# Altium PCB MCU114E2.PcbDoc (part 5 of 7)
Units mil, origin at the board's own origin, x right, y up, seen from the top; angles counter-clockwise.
Board outline 4153.94 x 2313.28 mil, 8 copper layers (Top Layer, GND 2, Signal Layer 3, Power 4, Power 5, Signal Layer 6, GND 7, Bottom), stack 61.2 mil thick; 444 components, 418 nets, 1811 pads, 981 vias.
Unrouted connection lines stored in the file: 3.
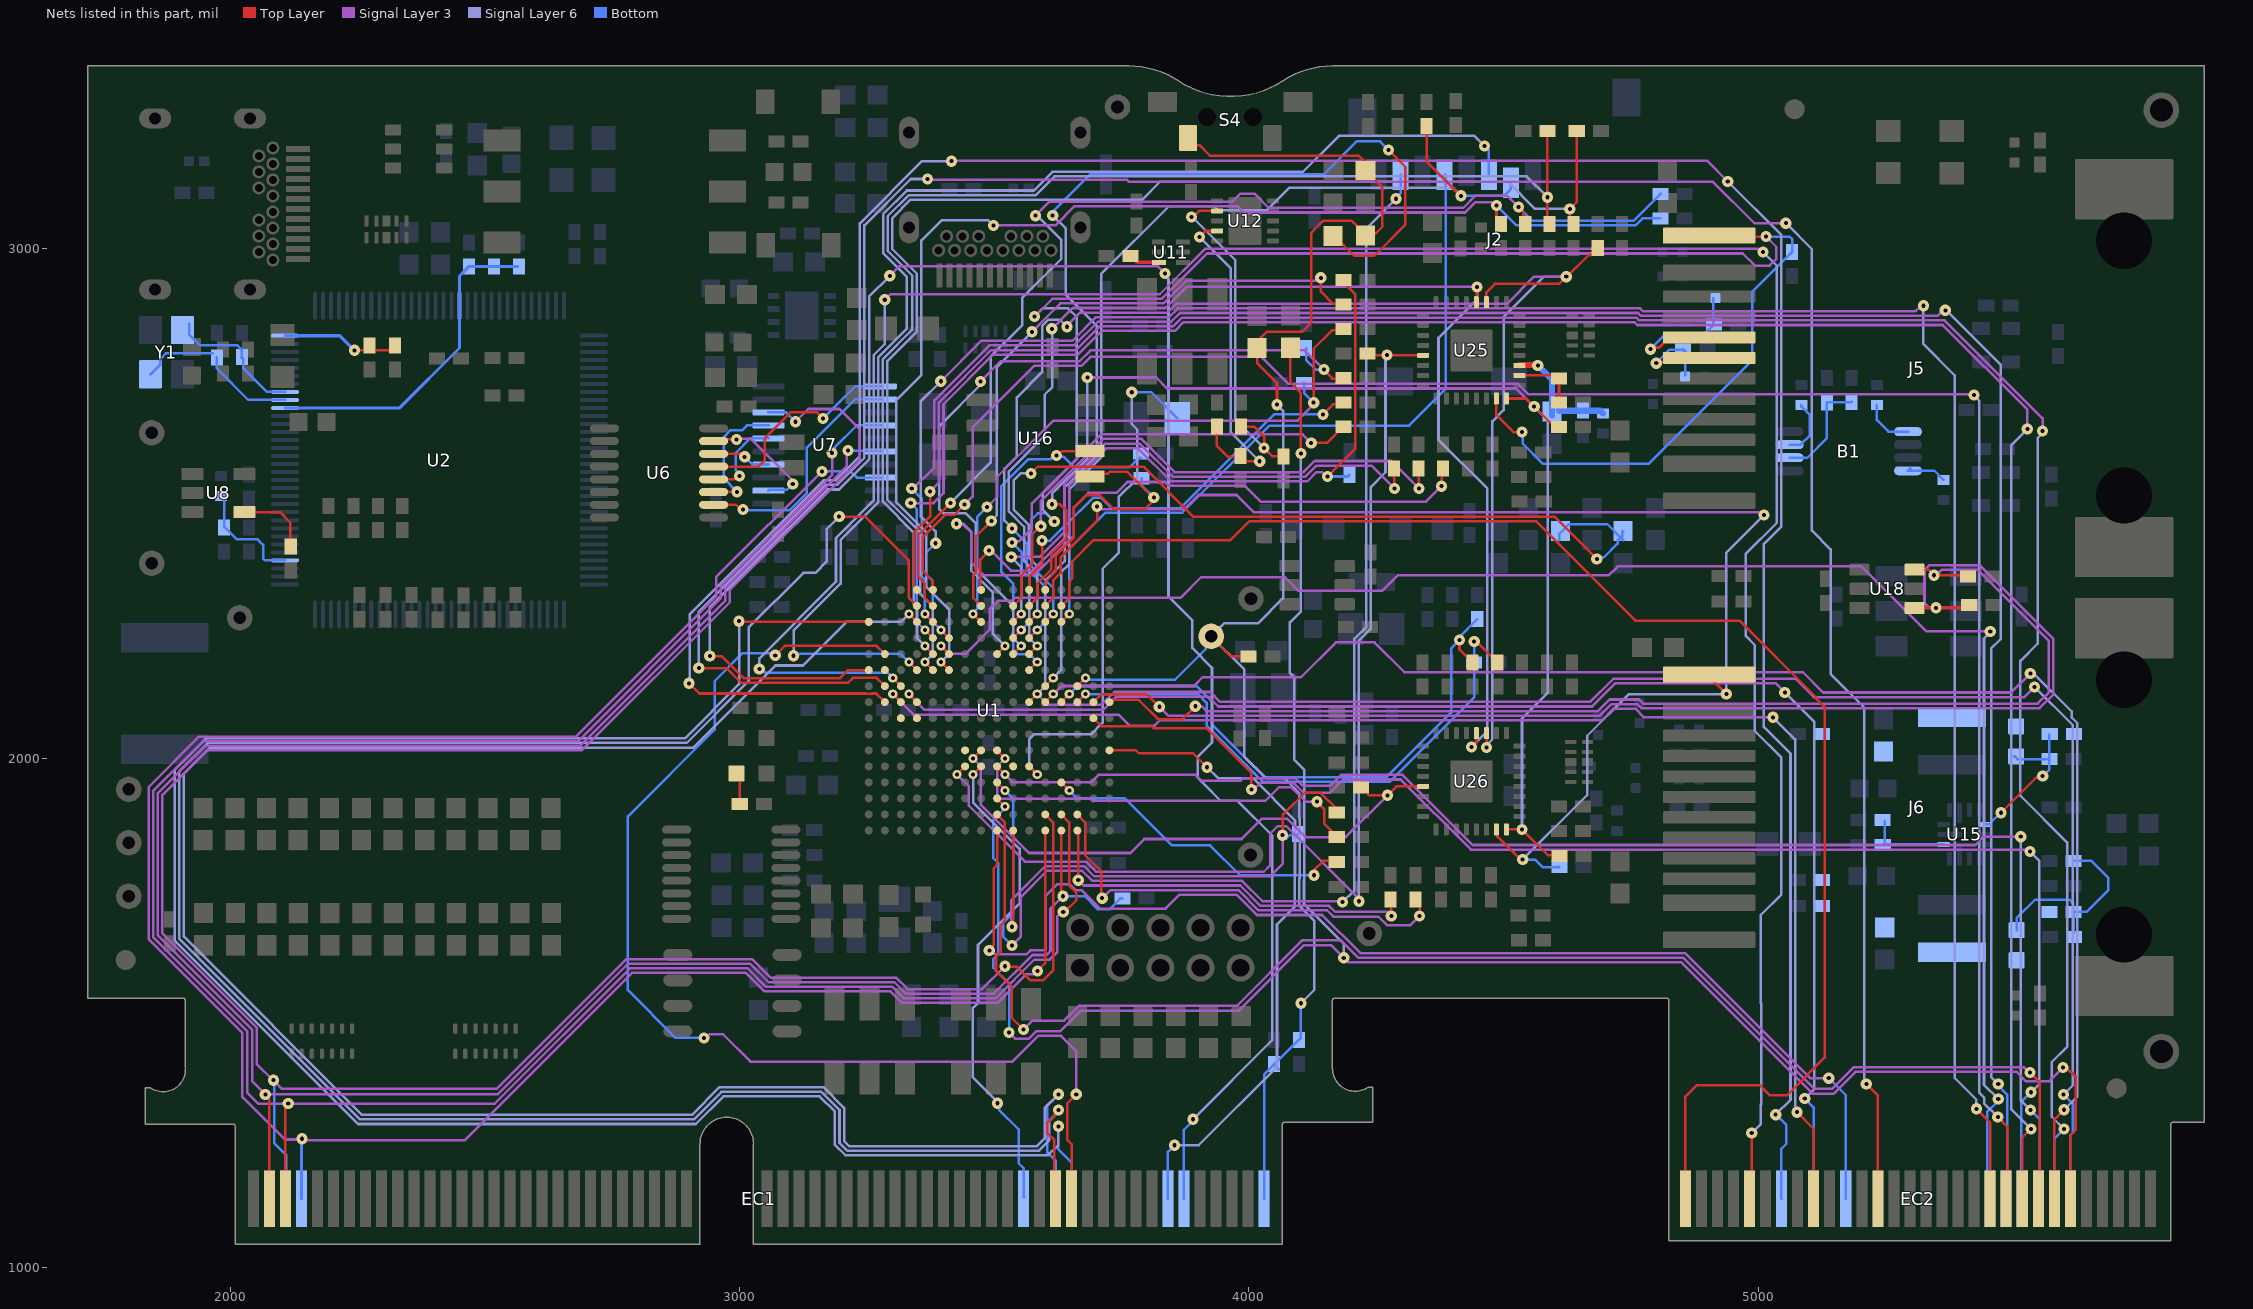
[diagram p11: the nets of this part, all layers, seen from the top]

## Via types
v1: diameter 22, hole 8, Top Layer to Bottom, tented both sides, 810 vias
v2: diameter 18, hole 8, Top Layer to Bottom, tented both sides, 153 vias
v3: diameter 19.68, hole 7.87, Top Layer to Bottom, tented both sides, 10 vias
v4: diameter 19.68, hole 7.87, Top Layer to Bottom, tented bottom, 4 vias
v5: diameter 19.68, hole 7.87, Top Layer to Bottom, tented top, 4 vias

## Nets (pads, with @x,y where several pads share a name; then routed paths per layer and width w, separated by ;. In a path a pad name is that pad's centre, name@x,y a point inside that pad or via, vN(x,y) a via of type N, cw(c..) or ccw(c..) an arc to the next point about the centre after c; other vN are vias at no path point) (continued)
MCU_GPIO90: EC2.159 U1.D6 | length 4360.5
  Top Layer w5: v2(3395.33,2251.77) U1.D6@3411.08,2236.02 ; v1(5428,1311.82) 5454.91,1284.92 EC2.159@5454.91,1135.27
  Signal Layer 3 w5: v1(3395,2740) 3474.27,2819.27 3653,2819.27 3699.51,2865.78 3843.42,2865.78 3860.64,2883 4767.76,2883 4773.31,2877.45 5308.42,2877.45 5319.23,2888.27 v1(5323.83,2888.27)
  Signal Layer 6 w5: v1(3385,2422) 3385,2445.4 3356,2474.4 3356,2701 v1(3395,2740) ; v1(5323.83,2888.27) 5323.83,2813.27 5385.37,2751.73 5385.37,1372.27 5428,1329.64 v1(5428,1311.82)
  Bottom w5: v1(3385,2422) 3366.4,2403.4 3366.4,2360.6 3379.33,2347.67 3379.33,2267.76 v2(3395.33,2251.77)
MCU_GPIO91: EC2.160 U1.E6 | length 3392.4
  Top Layer w5: v2(3395.33,2220.27) U1.E6@3411.08,2204.52
  Signal Layer 3 w5: v2(3395.33,2220.27) 3410.83,2204.77 3443.42,2204.77 3490.82,2252.17 3490.82,2292.84 3506.88,2308.9 3534.22,2308.9 3540.09,2314.77 3865.58,2314.77 3906.13,2355.31 3930.88,2355.31 4070.83,2355.32 4097.6,2328.54 4261.38,2328.54 4292.1,2359.27 4706.56,2359.27 4724.06,2376.77 5202.08,2376.77 5329.85,2249 v1(5455,2249)
  Signal Layer 6 w5: v1(5455,2249) 5455,2247.18 5442.83,2235.01 5442.83,1358.94 v1(5470.83,1330.94)
  Bottom w5: EC2.160@5454.91,1135.27 5449.05,1141.12 5449.05,1305.49 v1@5467.83,1324.27
MCU_GPIO92: EC2.161 U1.A5 | length 4038.8
  Top Layer w5: U1.A5@3379.58,2330.51 3379.58,2347.42 3359.83,2367.17 3359.83,2434.54 3403.11,2477.82 3421.39,2477.82 v1(3441.83,2498.27) ; v1(5469.94,1295.74) 5488.33,1277.35 5488.33,1135.27 EC2.161@5486.4,1135.27
  Signal Layer 3 w5: v1(3441.83,2498.27) 3457.33,2513.77 3457.33,2649.33 3578.27,2770.27 3671,2770.27 3688.5,2787.77 3873.97,2787.77 4024.96,2787.77 4077.96,2734.77 4528.06,2734.77 4548.56,2714.27 5421.73,2714.27 v1(5423,2713)
  Signal Layer 6 w5: v1(5423,2713) 5423,2712.13 5433.56,2701.57 5433.56,1343.28 5443.2,1333.64 5443.2,1322.48 v1(5469.94,1295.74)
MCU_GPIO93: EC2.162 U1.C5 | length 4347.2
  Top Layer w5: v2(3363.83,2283.26) U1.C5@3379.58,2267.52
  Signal Layer 3 w5: v1(3337.98,2529.48) 3340.67,2529.48 3382.33,2571.14 3382.33,2702.33 3490.27,2810.27 3552.37,2810.27 3656.72,2810.27 3703.24,2856.78 3847.15,2856.78 3864.37,2874 4764.03,2874 4769.58,2868.45 5351.42,2868.45 5362.23,2879.27 v1(5366.83,2879.27)
  Signal Layer 6 w5: v1(5366.83,2879.27) 5368.83,2879.27 5475.37,2772.73 5475.37,2233.54 5456.94,2215.1 5456.94,1374.16 v1(5470.83,1360.27)
  Bottom w5: v1(3337.98,2529.48) 3357.4,2510.07 3357.4,2356.88 3363.83,2350.44 v2(3363.83,2283.26) ; v1@5467.83,1360.27 5488.33,1339.77 5488.33,1137.2 EC2.162@5486.4,1135.27
MCU_GPIO94: EC2.163 U1.D5 | length 4374.6
  Top Layer w5: v2(3363.83,2251.77) U1.D5@3379.58,2236.02 ; EC2.163@5517.9,1135.27 5517.9,1255.33 v1(5534.83,1272.27)
  Signal Layer 3 w5: v1(3336.05,2500.98) 3380.98,2500.98 3400.33,2520.33 3400.33,2694.88 3497.73,2792.27 3544.92,2792.27 3664.18,2792.27 3710.69,2838.78 3854.6,2838.78 3871.82,2856 4756.58,2856 4762.12,2850.45 5361.65,2850.45 5527.83,2684.27 v1(5527.83,2646.27)
  Signal Layer 6 w5: v1(5527.83,2646.27) 5496.37,2614.8 5496.37,1310.73 v1(5534.83,1272.27)
  Bottom w5: v1@3340,2497 3347.84,2489.16 3347.84,2267.76 v2(3363.83,2251.77)
MCU_GPIO95: EC2.168 U1.A4 | length 4326.5
  Top Layer w5: U1.A4@3348.09,2330.51 3348.09,2332.55 3341.83,2338.81 3341.83,2442 3374,2474.17 v1(3374,2523.88)
  Signal Layer 3 w5: v1(3374,2523.88) 3391.33,2541.21 3391.33,2698.6 3494,2801.27 3548.65,2801.27 3660.45,2801.27 3706.96,2847.78 3850.87,2847.78 3868.1,2865 4760.3,2865 4765.85,2859.45 5365.37,2859.45 5557.83,2667 v1(5557.83,2642.27)
  Signal Layer 6 w5: v1(5557.83,2642.27) 5557.83,2638.34 5548.33,2628.84 5548.33,2225.02 5514.37,2191.06 5514.37,1926.36 5605.83,1834.9 5605.83,1433.5 5575.83,1403.5 5575.83,1296.27 v1(5599.83,1272.27)
  Bottom w5: EC2.168@5580.89,1135.27 5580.89,1253.33 v1(5599.83,1272.27)
MCU_GPIO96: EC1.93 U1.B4 | length 4421.2
  Top Layer w5: v1(3195.57,2474.48) 3246.52,2474.48 3331.96,2389.04 3331.96,2324.14 3331.96,2315.13 U1.B4@3348.09,2299.01 ; EC1.93@3620.35,1135.27 3617.83,1137.79 3617.83,1250.23 3604.33,1263.73 3604.33,1285.15 3625.83,1306.65 v1(3625.83,1309.27)
  Signal Layer 6 w5: v1@3192.32,2470.82 3171,2449.5 3171,2386 3148.85,2363.85 3125.1,2363.85 3017.83,2256.58 3017.83,2151.54 2896.29,2030 1956.46,2030 1900,1973.54 1900,1645.98 2254.98,1291 2910.27,1291 2964.54,1345.27 3160.77,1345.27 3196.13,1309.91 3196.13,1244.84 3211.21,1229.77 3587.86,1229.77 3608.29,1250.2 3608.29,1289.1 3625.83,1306.65 v1(3625.83,1309.27)
MCU_GPIO97: EC1.94 U1.C4 | length 4163.7
  Top Layer w5: v2(3332.34,2283.26) U1.C4@3348.09,2267.52
  Signal Layer 6 w5: v2(3332.34,2283.26) 3316.59,2267.51 3209.83,2267.51 3124.31,2182 3070.31,2182 2909.31,2021 1960.18,2021 1909,1969.82 1909,1649.71 2258.71,1300 2906.54,1300 2960.81,1354.27 3164.5,1354.27 3205.13,1313.64 3205.13,1248.57 3214.93,1238.77 3584.13,1238.77 3598.83,1253.47 3598.83,1313.27 v1(3625.83,1340.27)
  Bottom w5: EC1.94@3620.35,1135.27 3620.83,1135.74 3620.83,1209.27 3604.33,1225.77 3604.33,1318.77 v1(3625.83,1340.27)
MCU_GPIO98: EC1.95 U1.E2 | length 2328
  Top Layer w5: v1(3070,2202) 3088.65,2220.65 3268.97,2220.65 U1.E2@3285.09,2204.52 ; EC1.95@3651.85,1135.27 3651.85,1242.25 3643.33,1250.77 3643.33,1322.77 v1(3660.83,1340.27)
  Signal Layer 3 w5: v1(2930,1451) 2934.43,1451 2941.43,1458 2968,1458 3021.5,1404.5 3535.5,1404.5 3586,1455 3631,1455 3660.83,1425.17 v1(3660.83,1340.27)
  Bottom w5: v1(2930,1451) 2874.46,1451 2780.73,1544.73 2780.73,1885.63 2951.33,2056.24 2951.33,2151.51 3006.09,2206.27 3065.73,2206.27 v1(3070,2202)
MCU_GPIO99: EC1.96 U1.C1 | length 4090.6
  Top Layer w5: v1(2999,2269) 3000.49,2267.51 U1.C1@3253.6,2267.52
  Signal Layer 6 w5: v1(2999,2269) 2999,2145.44 2892.56,2039 1952.73,2039 1891,1977.27 1891,1642.26 2251.26,1282 2914,1282 2968.27,1336.27 3157.05,1336.27 3187.13,1306.18 3187.13,1241.11 3207.48,1220.77 3605.76,1220.77 3625.79,1240.8 v1(3625.79,1277.47) v1@3625.79,1281.86
  Bottom w5: v1@3625.83,1281.81 3625.83,1232.17 3651.85,1206.15 EC1.96@3651.85,1135.27
MCU_GPIO100: J2.3 U1.F4 | length 2547.2
  Top Layer w5: v2(3332.34,2188.77) U1.F4@3348.09,2173.03
  Signal Layer 6 w5: v1(3106.07,2201.16) 3106.07,2250.51 3198.33,2342.77 3198.33,2428.6 3272.33,2502.6 3272.33,2787.33 3328.6,2843.6 3328.6,2944.94 3281.83,2991.71 3281.83,3067.83 3328.5,3114.5 3577.77,3114.5 3614.27,3151 4105.56,3151 4176.33,3221.77 4442.23,3221.77 v1(4462,3202)
  Bottom w5: v1(3106.07,2201.16) 3109.32,2204.41 3117.14,2204.41 3117.5,2204.77 3316.34,2204.77 v2(3332.34,2188.77) ; v1(4462,3202) 4470.75,3193.25 J2.3@4470.75,3145.39
MCU_GPIO101: J2.7 U1.N9 | length 2603.9
  Top Layer w5: U1.N9@3505.57,1952.55 3520.87,1937.25 v2@3520.87,1936.69
  Signal Layer 3 w5: v1(3534.83,1632.69) 3535.12,1632.69 3552.33,1649.89 3552.33,1727.77 3603.75,1779.19 3672.54,1779.19 3692.54,1759.19 3986.54,1759.19 4026.46,1719.27 4182.12,1719.27 v1(4183.76,1717.64)
  Signal Layer 6 w5: v1(4183.76,1717.64) 4206.83,1740.71 4206.83,2234.55 4230.33,2258.05 4230.33,3039.77 v1(4288.83,3098.27)
  Bottom w5: v2(3521.31,1936.81) 3537.06,1921.06 3537.06,1900.78 3537.04,1894.54 ; v1(3534.83,1632.69) 3517.33,1650.19 3517.33,1676.52 3537.06,1696.25 3537.06,1894.52 ; v1(4288.83,3098.27) 4288.83,3100.36 4297.52,3109.05 J2.7@4297.52,3145.39
MCU_GPIO102: J2.5 U1.C13 | length 1440.2
  Top Layer w5: U1.C13@3631.55,2267.52 v2(3647.3,2283.26)
  Bottom w5: v2(3647.3,2283.26) 3647.3,2411.35 3717.95,2482 3869,2482 4040,2653 4314.34,2653 4385.83,2724.49 4385.83,3099.27 4385.83,3143.7 J2.5@4384.14,3145.39
MCU_GPIO103: J2.2 R36.1 U1.G12 | length 1924.4
  Top Layer w5: U1.G12@3600.06,2141.53 v2(3615.8,2157.28) ; R36.1@4348.51,3241.06 4348.51,3171.49 v1(4416,3104)
  Signal Layer 6 w5: v2(3615.8,2157.28) 3631.3,2172.78 3631.3,2365.42 3647.33,2381.45 3647.33,2527.99 3709.83,2590.49 3709.83,2950.41 3842.93,3083.5 3931.68,3083.5 3939.44,3075.74 4035.06,3075.74 4078.81,3119.5 4400.5,3119.5 v1(4416,3104)
  Bottom w5: v1(4416,3104) 4500.81,3104 4514.06,3117.25 J2.2@4514.06,3129.65
MCU_GPIO104: EC2.121 U1.B13 | length 2968.2
  Top Layer w5: U1.B13@3631.55,2299.01 3647.31,2314.77 3647.3,2347.31 3653.08,2353.09 3653.08,2386.52 3694.56,2428 3963.58,2428 4000.35,2464.77 4564.23,2464.77 4758.73,2270.27 4962.83,2270.27 5112.42,2120.68 5112.42,2118.41 5130,2100.83 5130,1412.44 5055.83,1338.27 5022.83,1338.27 5003.18,1357.92 4878.83,1357.92 4856.48,1335.57 EC2.121@4856.48,1135.27
MCU_GPIO105: EC1.108 U1.L16 | length 1295.1
  Top Layer w5: U1.L16@3726.04,2015.55 3777.8,2015.55 3783.58,2009.77 3858.08,2009.77 3890.33,2009.77 v1(3917.83,1982.27)
  Signal Layer 6 w5: v1(3853.83,1240.27) 3901.27,1240.27 4055,1394 4055,1674 4090,1709 4090,1768 4090.33,1768.33 4090.33,1877.99 4007.55,1960.77 3939.33,1960.77 v1(3917.83,1982.27)
  Bottom w5: EC1.108@3840.83,1135.27 3840.83,1227.26 v1(3853.83,1240.27)
MCU_GPIO106: EC1.110 U1.F1 | length 3815
  Top Layer w5: v1(2941.63,2200.62) 2964.38,2200.62 3007.81,2157.19 3197.19,2157.19 3213,2173 3225.56,2173 ; 3225.59,2173.03 U1.F1@3253.6,2173.03
  Signal Layer 3 w5: v1(3295,2947) 3314,2966 3820.58,2966 v1(3835.27,2951.31)
  Signal Layer 6 w5: v1(2941.63,2200.62) 2941.63,2296.63 3172.5,2527.5 3195.33,2527.5 3254.33,2586.5 3254.33,2906.33 v1(3295,2947) ; v1(3835.27,2951.31) 3835.27,2946.71 3842,2939.98 3842,2317.1 3888.83,2270.27 3888.83,2216.02 3927.33,2177.52 3927.33,2031.02 3898.96,2002.65 3898.96,1961.89 3913.33,1947.52 3944.58,1916.27 3977.56,1916.27 4046,1847.83 4046,1447.44 v1(3889.83,1291.27)
  Bottom w5: EC1.110@3872.32,1135.27 3872.32,1270.76 3889.83,1288.27 v1(3889.83,1291.27)
MCU_GPIO107: U1.F2
MCU_GPIO108: EC2.145 U1.G2 | length 5276.9
  Top Layer w5: v1(2920,2177) 2974,2177 3002.81,2148.19 3213.19,2148.19 3222.65,2157.65 3268.97,2157.65 U1.G2@3285.09,2141.53 ; v1(5211.83,1360.27) 5234.43,1337.67 EC2.145@5234.43,1135.27
  Signal Layer 3 w5: v1(3369,3137) 3370.23,3135.77 3760.1,3135.77 3763.87,3132 4910.1,3132 4991.83,3050.27 v1(5053.83,3050.27)
  Signal Layer 6 w5: v1(2920,2177) 2920,2287.73 3168.77,2536.5 3191.6,2536.5 3245,2589.9 3245,3045.98 3336.02,3137 v1(3369,3137) ; v1(5053.83,3050.27) 5105,2999.1 5105,2446.85 5141.83,2410.02 5141.83,2165.27 5208,2099.1 5208,1364.1 v1(5211.83,1360.27)
MCU_GPIO109: EC2.129 U1.G3 | length 4836.3
  Top Layer w5: v2(3300.84,2157.28) U1.G3@3316.59,2141.53 ; EC2.129@4982.46,1135.27 4986.83,1139.63 v1(4986.83,1264.27)
  Signal Layer 3 w5: v1(3285,2900) 3285.46,2900 3296.24,2910.78 3824.78,2910.78 3913.8,2999.8 4998.6,2999.8 5004.4,2994 v1(5009,2994)
  Signal Layer 6 w5: v1(3038.83,2175.27) 3038.83,2196 3189.33,2346.5 3189.33,2432.33 3263.33,2506.33 3263.33,2791.06 3285,2812.73 v1(3285,2900) ; v1(4986.83,1264.27) 5005,1282.44 5005,1320.69 5005.33,1321.02 5005.33,1519.21 5005,1519.54 5005,1692.73 5045,1732.73 5045,2001.64 4992.83,2053.81 4992.83,2222.17 4975.33,2239.67 4975.33,2401.52 5036,2462.19 5036,2967 v1(5009,2994)
  Bottom w5: v1(3038.83,2175.27) 3042.99,2175.27 3050.26,2168 3290.12,2168 v2(3300.84,2157.28)
MCU_GPIO110: EC2.134 U1.H2 | length 5328.4
  Top Layer w5: v1(2901,2147) 2920.94,2127.06 3246.33,2127.06 3247.23,2126.16 3259.97,2126.16 3260.87,2127.06 3268.07,2127.06 U1.H2@3285.09,2110.03
  Signal Layer 3 w5: v1(3416,3172) 3416.5,3172.5 4899.6,3172.5 v1(4939.83,3132.27)
  Signal Layer 6 w5: v1(2901,2147) 2902.5,2148.5 2902.5,2282.96 3165.05,2545.5 3187.87,2545.5 3236,2593.63 3236,3049.7 3358.3,3172 v1(3416,3172) ; v1(4939.83,3132.27) 5045,3027.1 5045,2454.69 5010.83,2420.52 5010.83,2061.27 5050.33,2021.77 5063,2009.1 5063,1329.44 v1(5033.83,1300.27)
  Bottom w5: v1(5033.83,1300.27) 5034.83,1300.27 5054.83,1280.27 5054.83,1243.27 5044.83,1233.27 5044.83,1135.89 EC2.134@5045.46,1135.27
MCU_GPIO111: EC2.137 U1.H3 | length 2774.7
  Top Layer w5: v2(3300.84,2125.78) U1.H3@3316.59,2110.03 ; v1(5075.83,1305.27) 5108.45,1272.65 EC2.137@5108.45,1135.27
  Signal Layer 3 w5: v2(3300.84,2125.78) 3341.1,2085.52 3743.83,2085.52 3765.36,2064 3814.83,2064 3825.41,2074.58 4692.41,2074.58 4715.1,2097.27 4758.42,2097.27 4775.42,2080.27 v1(5028.83,2080.27)
  Signal Layer 6 w5: v1(5028.83,2080.27) 5072,2037.1 5072,1316.7 5072.58,1316.12 5072.58,1308.52 v1(5075.83,1305.27)
MCU_GPIO112: EC2.138 U1.H4 | length 2832.7
  Top Layer w5: v2(3332.34,2125.78) U1.H4@3348.09,2110.03
  Signal Layer 3 w5: v2(3332.34,2125.78) 3363.09,2095.03 3713.94,2095.03 3739.91,2121 3920.27,2121 3939.69,2101.58 4673.43,2101.58 4718.85,2147 5034.1,2147 v1(5051.83,2129.27)
  Signal Layer 6 w5: v1(5051.83,2129.27) 5110,2071.1 5110,1351 v1(5091,1332)
  Bottom w5: v1(5091,1332) 5108.45,1314.55 EC2.138@5108.45,1135.27
MCU_GPIO113: U1.J3 | length 0
MCU_GPIO114: U1.J4
MCU_GPIO115: EC2.169 R212.1 U1.P9 | length 4340.6
  Top Layer w5: U1.P9@3505.57,1921.06 v2(3521.31,1905.31) ; R212.1@4081.04,2805.79 4081.04,2737.73 4102,2716.77 v1(4102,2598) ; v1(5598,1393) 5604.1,1393 5623,1374.1 5623,1270.69 5612.39,1260.07 EC2.169@5612.39,1135.27
  Signal Layer 3 w5: v1(3529.06,1461.57) 3541.63,1449 3567.27,1449 3582.27,1464 3629,1464 3669.27,1504.27 3979,1504.27 4107.73,1633 4161.33,1633 v1(4186.06,1608.27) 4195.06,1599.27 4848.83,1599.27 5106.33,1341.77 5148.06,1341.77 5190.56,1384.27 5507.08,1384.27 5525.58,1365.77 5570.77,1365.77 v1(5598,1393)
  Signal Layer 6 w5: v1(4102,2598) 4102,2288.19 4080.33,2266.52 4080.33,2167.67 4088.59,2159.41 4088.59,1997.45 4108.33,1977.71 4108.33,1760.54 4108,1760.21 4108,1713.83 4186.06,1635.77 v1(4186.06,1608.27)
  Bottom w5: v2(3521.31,1905.31) 3521.31,1901.79 3498,1878.48 3498,1803.83 3507.8,1794.03 3507.8,1615.51 3498,1605.71 3498,1588.73 3529.06,1557.67 v1(3529.06,1461.57) ; v1@3526,1463 v1@3526.82,1463.82
MCU_GPIO116: EC2.170 R78.1 U1.H11 | length 5194.6
  Top Layer w5: U1.H11@3568.56,2110.03 v2(3584.31,2125.78) ; R78.1@4168.13,3024.77 4206.63,2986.27 4245.83,2986.27 4307,3047.44 4307,3161 v1(4274,3194)
  Signal Layer 3 w5: v2(3584.31,2125.78) 3604.86,2105.22 3710.76,2105.22 3735.53,2130 3924,2130 3943.42,2110.58 4669.7,2110.58 4715.12,2156 5073,2156 5109,2120 5522,2120 v1(5542,2140)
  Signal Layer 6 w5: v2(3584.31,2125.78) 3600.3,2141.78 3600.3,2349.05 3638.33,2387.07 3638.33,2531.72 3700.83,2594.22 3700.83,2849.17 3640.53,2909.47 3640.53,3039.69 v1(3614.58,3065.64) ; v1(5542,2140) 5617,2065 5617,1358 v1(5599,1340)
  Bottom w5: v1@3611.11,3069.11 3688.12,3146.12 4146.68,3146.12 4211.33,3210.77 4257.23,3210.77 v1(4274,3194) ; v1(5599,1340) 5617.5,1321.5 5617.5,1265.19 5612.39,1260.07 EC2.170@5612.39,1135.27
MCU_GPIO119: U1.M10
MCU_GPIO120: R85.2 U1.M11 | length 1046.4
  Top Layer w5: U1.M11@3568.56,1984.05 v2(3584.31,1968.3)
  Signal Layer 6 w5: v2(3584.31,1968.3) 3568.81,1983.8 3568.81,2037.71 3577.89,2046.79 3685.21,2046.79 3689.63,2046.79 3712.83,2070 3712.83,2372 3744.1,2403.27 3744.1,2512.38 3780.78,2549.05 3780.78,2644.77 3769.92,2655.63 v1(3769.92,2718.39)
  Bottom w5: v1(3769.92,2718.39) 3808.33,2718.39 R85.2@3858.83,2667.89
MCU_GPIO122: U1.L7 | length 0
MCU_GPIO123: R108.2 U1.M7 U25.21 | length 2255.2
  Top Layer w5: v2(3426.83,1968.3) U1.M7@3442.57,1984.05 ; R108.2@4232.06,2792.69 4233.9,2790.84 U25.21@4341.95,2790.84
  Signal Layer 3 w5: v2(3426.83,1968.3) 3449.83,1945.3 3449.83,1907.27 3559.91,1797.19 3679.99,1797.19 3699.68,1777.5 3953.58,1777.5 3953.89,1777.19 4029,1777.19 4041.57,1789.76 4041.57,1851.77 4056.3,1866.5 4073.25,1866.5 4210.07,1729.67 ; 4210.07,1729.63 4215.83,1723.87 v1(4215.83,1719.27)
  Signal Layer 6 w5: v1(4215.83,1719.27) 4215.83,2230.82 4239.33,2254.32 4239.33,2532.77 4267.94,2561.37 4267.94,2788.37 v1(4270.83,2791.27)
MCU_GPIO124: R142.2 U1.L8 U26.21 | length 1172.1
  Top Layer w5: v2(3458.32,1999.8) U1.L8@3474.07,2015.55 ; R142.2@4219.5,1942.8 4223.44,1942.8 4232.75,1933.49 4232.75,1930.2 4235.68,1927.27 v1(4271.83,1927.27) 4289.41,1944.84 U26.21@4341.95,1944.84
  Signal Layer 3 w5: v2(3458.32,1999.8) 3473.82,1984.3 3473.82,1908.55 3568.37,1814 3767,1814 3794.45,1841.45 3985.45,1841.45 4025.27,1881.27 4074.31,1881.27 4110.54,1845.03 4189.6,1845.03 v1(4271.83,1927.27)
MCU_GPIO125: EC1.90 U1.M8 | length 967
  Top Layer w5: v2(3458.32,1968.3) U1.M8@3474.07,1984.05
  Signal Layer 6 w5: v2(3458.32,1968.3) 3458.32,1913.53 3549.83,1822.02 3549.83,1715.27 3468,1633.44 3468,1519.73 3458,1509.73 3458,1373.42 v1@3506.24,1325.18
  Bottom w5: v1(3506.27,1322.81) 3509.45,1319.63 3509.45,1309.82 3548,1271.27 3548,1204.87 3557.91,1194.96 3557.91,1139.2 EC1.90@3558.43,1138.69
MCU_GPIO126: EC2.142 U1.T9 | length 2442
  Top Layer w5: v1(3490.3,1622.75) 3490.3,1625.11 3499.37,1634.18 3499.37,1784.02 3505.57,1790.22 U1.T9@3505.57,1858.07
  Signal Layer 3 w5: v1(3490.3,1622.75) 3494.16,1622.75 3501.73,1615.19 3563.46,1615.19 3571.03,1622.75 3598.39,1622.75 3601.32,1625.68 3601.32,1730.32 3624,1753 3647.81,1753 3659.89,1740.92 3671.43,1740.92 3707.58,1704.77 3836.08,1704.77 3863.5,1732.19 3975.36,1732.19 4015.28,1692.27 4143.73,1692.27 4218.73,1617.27 4856.29,1617.27 5101.56,1372 v1(5138,1372)
  Bottom w5: v1(5138,1372) 5171.44,1338.56 EC2.142@5171.44,1135.27
MCU_GPIO127: EC2.165 U1.R9 | length 2908.3
  Top Layer w5: U1.R9@3505.57,1889.56 3520.94,1874.19 3520.94,1680.13 3513,1672.19 3513,1620.71 3503.37,1611.08 3503.37,1598.93 3503.37,1582.5 3534.1,1551.78 3534.1,1490.63 v1(3557.5,1467.23) ; v1(5532.83,1383.27) 5552.33,1363.77 5552.33,1135.27 EC2.165@5549.39,1135.27
  Signal Layer 3 w5: v1(3557.5,1467.23) 3575.26,1485 3637.27,1485 3666.27,1514 3976,1514 4105,1643 4180,1643 4214.73,1608.27 4852.56,1608.27 5110.06,1350.77 5144.33,1350.77 5186.83,1393.27 5521.4,1393.27 5531.4,1383.27 v1(5532.83,1383.27)
MCU_GPIO128: EC2.166 U1.M9 | length 2841.6
  Top Layer w5: U1.M9@3505.57,1984.05 v2(3521.31,1968.3)
  Signal Layer 3 w5: v2(3521.31,1968.3) 3536.81,1952.8 3690.12,1952.8 3704.59,1967.27 3895.35,1967.27 3906.85,1955.77 3983.33,1955.77 3988.33,1960.77 4090.81,1960.77 4105.98,1945.61 4159.37,1945.61 4181.04,1967.27 4301.56,1967.27 4439.09,1829.73 5425.83,1829.73 5442.1,1846 v1(5515,1846)
  Signal Layer 6 w5: v1(5515,1846) 5515.33,1845.67 5515.33,1327.77 v1(5533.83,1309.27)
  Bottom w5: v1(5533.83,1309.27) 5552.33,1290.77 5552.33,1138.21 EC2.166@5549.39,1135.27
MCU_GPIO129: R91.2 U1.L9 | length 844.1
  Top Layer w5: U1.L9@3505.57,2015.55 v2(3521.31,1999.8) ; v1(4133.35,1914.68) 4147.33,1900.7 4147.33,1871.5 R91.2@4171.71,1847.13 ; R91.2@4180.88,1852.02 R91.2@4184.81,1852.02
  Signal Layer 3 w5: 3505.81,1979.12 3505.81,1925.97 3510.98,1920.81 3690.26,1920.81 3694.8,1916.27 4031.93,1916.27 4058.43,1942.77 4068.58,1942.77 4083.36,1942.77 4111.45,1914.68 v1(4133.35,1914.68) ; 3505.83,1979.14 3505.83,1984.31 v2(3521.31,1999.8)
MCU_GPIO130: R146.2 R155.1 U1.T10 | length 1087.9
  Top Layer w5: v1(3534.83,1669.27) 3536.83,1671.27 3536.83,1789.08 3537.06,1789.32 U1.T10@3537.06,1858.07 ; v1@4066.54,1849 4066.54,1889.41 4109.4,1932.27 4109.49,1932.18 4140.6,1932.18 4171.71,1901.07 R155.1@4171.71,1894.55
  Signal Layer 3 w5: v1(3534.83,1669.27) 3532.95,1671.15 3532.95,1721.11 3600.02,1788.19 3676.26,1788.19 3696.26,1768.19 4041.64,1768.19 4066,1792.54 v1(4066,1849)
  Bottom w5: v1@4073,1842 4079.85,1848.85 4093.74,1848.85 R146.2@4096.24,1851.36
MCU_GPIO131: R203.2 U1.N13 | length 647.8
  Top Layer w5: U1.N13@3631.55,1952.55 v2(3647.3,1936.81) ; v1(4127.83,1770.27) 4127.83,1780.36 4146.12,1798.64 4170.65,1798.64 R203.2@4171.71,1799.7 ; R203.2@4173.8,1797.61 4180.88,1804.69 R203.2@4184.81,1804.69
  Bottom w5: v2(3647.3,1936.81) 3662.74,1921.37 3672.31,1921.37 3672.37,1921.31 3685.21,1921.31 3685.28,1921.37 3756.36,1921.37 3848.65,1829.08 3923.48,1829.08 3982.29,1770.27 v1(4127.83,1770.27)
MCU_GPIO132: R144.2 U1.T14 | length 782.1
  Top Layer w5: U1.T14@3663.05,1858.07 3664.59,1856.52 3664.59,1761.97 v1@3665.87,1760.69 ; R144.2@4278,1723.38 4279.4,1721.98 v1(4279.4,1690.58)
  Signal Layer 3 w5: v1(3664.87,1760.69) 3675.37,1750.19 3982.81,1750.19 4022.73,1710.27 4157.29,1710.27 4169.29,1698.27 4274.4,1698.27 4282.4,1690.27 v1@4285.83,1690.27
MCU_GPIO133: EC2.164 U1.J15 | length 2697.3
  Top Layer w5: U1.J15@3694.54,2078.54 3710.29,2062.79 3809.75,2062.79 3813.8,2058.75 3917.25,2058.75 4004.74,1971.26 v1(4004.74,1938.83)
  Signal Layer 3 w5: v1@4009.75,1939.35 4022.17,1951.77 4087.09,1951.77 4106.59,1932.27 4158.76,1932.27 4184.76,1958.27 4297.83,1958.27 4435.37,1820.73 5529.27,1820.73 v1(5533,1817)
  Signal Layer 6 w5: v1(5533,1817) 5551.33,1798.67 5551.33,1360.77 v1(5534.83,1344.27)
  Bottom w5: EC2.164@5517.9,1135.27 5516.33,1136.83 5516.33,1325.77 v1(5534.83,1344.27)
MCU_GPIO134: R110.2 U1.R14 | length 887.3
  Top Layer w5: U1.R14@3663.05,1889.56 3678.42,1874.19 3678.42,1809.58 3710.35,1777.65 3710.35,1726.75 v1(3711.83,1725.27) ; v1@4332.44,1692.66 v1(4334.83,1690.27) 4334.83,1720.67 R110.2@4332.44,1723.06
  Signal Layer 3 w5: v1(3711.83,1725.27) 3727.75,1741.19 3979.09,1741.19 4019,1701.27 4153.56,1701.27 4165.56,1689.27 4253.73,1689.27 4270.73,1672.27 4316.83,1672.27 v1(4334.83,1690.27)
MCU_GPIO141: R145.1 R152.1 U1.H13 | length 1190.6
  Top Layer w5: U1.H13@3631.55,2110.03 v2(3647.3,2125.78) ; v1(4413.21,2232.18) 4413.21,2213.17 R152.1@4438.5,2187.89
  Bottom w5: v2(3647.3,2125.78) 3663.29,2141.78 3896.63,2141.78 3927.33,2111.08 3927.33,2066.44 4004.15,1989.63 4004.15,1989.3 4014.4,1979.05 4014.72,1979.05 4030.78,1963 4270.09,1963 4396.83,2089.75 4396.83,2215.8 v1(4413.21,2232.18) 4413.21,2238.25 R145.1@4448.03,2273.07
MCU_GPIO142: R133.1 R153.1 U1.H14 | length 1123.5
  Top Layer w5: U1.H14@3663.05,2110.03 v2(3678.79,2125.78) ; v1(4442,2229) 4446.22,2229 R153.1@4487.33,2187.89
  Bottom w5: v2(3678.79,2125.78) 3899.9,2125.78 3917,2108.69 3917,2064.05 3995.15,1985.9 3995.15,1985.58 4010.67,1970.05 4011,1970.05 4027.05,1954 4276.64,1954 4442.06,2119.42 R133.1@4442.06,2187.89 4442.06,2228.94 v1(4442,2229)
MCU_GPIO145: R139.1 U1.H15 U18.1 | length 2559.1
  Top Layer w5: U1.H15@3694.54,2110.03 3710.29,2125.78 3799.22,2125.78 v1(3824,2101)
  Top Layer w6.25: U18.1@5306.57,2295.28 v1(5348.83,2295.27) 5408.4,2295.27 R139.1@5413.81,2300.69
  Signal Layer 3 w5: v1(3824,2101) 3824,2100.82 3841.24,2083.58 4688.69,2083.58 4711.38,2106.27 4762.15,2106.27 4770.15,2098.27 5551.83,2098.27 5579,2125.44 5579,2233.83 5433.74,2379.09 5335.94,2379.09 5326,2369.15 5326,2304.38 5333.89,2296.49 5347.61,2296.49 v1(5348.83,2295.27)
MCU_GPIO146: R140.1 U1.H16 U18.3 | length 2397.3
  Top Layer w5: U1.H16@3726.04,2110.03 3728.95,2110.03 3733.68,2114.77 3783.23,2114.77 3821.25,2076.75 3869.33,2076.75 v1(3894.67,2102.09) ; U18.3@5306.57,2370.09 5333.75,2370.09 5344.57,2359.27 5409.23,2359.27 R140.1@5411.81,2356.69
  Signal Layer 3 w5: v1(3894.67,2102.09) 3907.49,2102.09 3917,2092.58 4684.96,2092.58 4707.65,2115.27 4765.88,2115.27 4773.88,2107.27 5548.1,2107.27 5570,2129.17 5570,2230.1 5430.01,2370.09 5360.18,2370.09 5349.36,2359.27 v1(5344.83,2359.27)
MCU_GPIO147: EC2.167 U1.H12 | length 3131
  Top Layer w5: U1.H12@3600.06,2110.03 v2(3615.8,2125.78) ; EC2.167@5580.89,1135.27 5580.89,1291.21 5599.68,1310 v1(5600,1310)
  Signal Layer 3 w5: v2(3615.8,2125.78) 3631.8,2141.78 3891.78,2141.78 3909,2159 4102,2159 4170.35,2227.35 4246.56,2227.35 4305.14,2168.77 4985.99,2168.77 4986.22,2169 5087,2169 5127,2129 5496.12,2129 v1(5533.74,2166.62)
  Signal Layer 6 w5: v1(5533.74,2166.62) 5540.13,2166.62 5615,2091.75 5615,2079.73 5626,2068.73 5626,1336 v1(5600,1310)
MCU_GPIO148: J5.1 R129.2 U1.C12 U25.31 | length 3499
  Top Layer w5: U1.C12@3600.06,2267.52 v2(3615.8,2283.26) ; U25.31@4485.65,2706.2 4485.65,2673.7 4505.58,2653.77 4519.08,2640.27 v1(4535.83,2640.27) ; J5.1@4903.31,3025.92 4905.23,3024 v1(5015,3024)
  Signal Layer 3 w5: v1(3579,2867) 3613.78,2901.78 3828.51,2901.78 3917.53,2990.8 4969.2,2990.8 4993,2967 5022,2967 5035,2980 5035,3004 v1(5015,3024)
  Signal Layer 6 w5: v1(3579,2867) 3595,2883 3645.1,2883 3661.86,2866.24 3661.86,2586.74 3594.83,2519.71 3594.83,2488.17 3617.83,2465.17 v1(3617.83,2464.62)
  Bottom w5: v2(3615.8,2283.26) 3615.8,2333.72 3572.51,2377.01 3572.51,2411.05 3572.51,2467.95 3585.32,2480.76 3601.69,2480.76 v1(3617.83,2464.62) ; v1(4535.83,2640.27) 4537.44,2638.66 4537.44,2617.29 4576.46,2578.27 4784.83,2578.27 4988.21,2781.64 4988.21,2915.83 R129.2@5066,2993.62 5066,3019.21 5061.21,3024 v1(5015,3024)
MCU_GPIO149: J6.1 R163.1 U1.B12 U26.31 | length 2775.5
  Top Layer w5: U1.B12@3600.06,2299.01 3616.18,2315.13 3616.18,2349.61 3630.05,2363.49 3630.05,2394.1 3701.83,2465.88 v1(3701.83,2494.27) ; U26.31@4485.65,1860.2 4487.65,1858.2 4487.65,1846.01 4532.63,1801.03 v1(4537.23,1801.03) ; J6.1@4903.31,2164.27 4903.31,2159.69 v1(4937,2126)
  Signal Layer 3 w5: v1(3701.83,2494.27) 3706.43,2494.27 3712.18,2488.52 3872.52,2488.52 3900.77,2516.77 3975.74,2516.77 4009.74,2482.77 5000.73,2482.77 5006.23,2477.27 v1(5010.83,2477.27)
  Signal Layer 6 w5: v1(4537.23,1801.03) 4664,1927.8 4664,2044.19 4745.81,2126 v1(4937,2126) 4937,2403.44 v1(5010.83,2477.27)
  Bottom w5: v1(4537.23,1801.03) 4561.28,1801.03 4576.69,1785.61 4608.21,1785.61 R163.1@4609.21,1786.61
MCU_GPIO150: R105.1 U1.A12 U16.5 | length 557.5
  Top Layer w5: U1.A12@3600.06,2330.51 3600.06,2346.22 3621.05,2367.21 3621.05,2397.83 3656.33,2433.11 3656.33,2492.52 3680.58,2516.77 3706.85,2516.77 3733.86,2489.76 3734.03,2489.93 3796.93,2489.93 3815,2508 3760.5,2562.5 3726.75,2562.5 3722.25,2558 3711.39,2558 U16.5@3707.08,2562.31 ; U16.5@3679.87,2549.69 U16.5@3679.87,2552.35
  Bottom w5: R105.1@3789.38,2549.62 3789.38,2535.35 v1(3813.18,2511.56)
MCU_GPIO151: R106.1 U1.F11 U16.6 | length 795.7
  Top Layer w5: U1.F11@3568.56,2173.03 v2(3584.31,2188.77) ; v1(3622.03,2594) 3624.46,2594 3633.46,2603 U16.6@3688.28,2603
  Bottom w5: v2(3584.31,2188.77) 3568.81,2204.27 3546.89,2204.27 3537.31,2213.85 3537.31,2342 3514,2365.31 3514,2534 3567.29,2587.29 3610.72,2587.29 3617.43,2594 v1(3622.03,2594) 3624.1,2591.93 3636.12,2591.93 3656.55,2571.5 3766.02,2571.5 3775.13,2580.61 3775.13,2580.69 3784.44,2590 R106.1@3788.38,2590
MCU_GPIO152: U1.E11 U25.12 U26.12 | length 2621.2
  Top Layer w5: U1.E11@3568.56,2204.52 v2(3584.31,2220.27)
  Top Layer w6.25: v1(4436.83,2022.27) 4446.28,2031.72 U26.12@4446.28,2049.17 ; U25.12@4446.28,2895.17 4447.83,2896.73 v1(4447.83,2925.27)
  Signal Layer 3 w5: v1(3613,2843) 3653.78,2883.78 3835.96,2883.78 3877.45,2925.27 v1(4447.83,2925.27)
  Signal Layer 6 w5: v2(3584.31,2220.27) 3568.31,2236.27 3568.31,2377.52 3558.83,2387 3558.83,2454.27 3528.83,2484.27 3528.83,2562.83 3599,2633 3599,2713.48 3614,2728.48 3614,2842 v1(3613,2843) ; v1(4436.83,2022.27) 4468,2053.44 4468,2529.1 4372,2625.1 4372,2825 4447.83,2900.83 v1(4447.83,2925.27)
MCU_GPIO153: R107.1 U1.D11 U25.11 U26.11 | length 3084.5
  Top Layer w5: U1.D11@3568.56,2236.02 v2(3584.31,2251.77) ; U26.11@4465.96,2049.17 4466.34,2048.8 v1(4466.34,2021.19) ; U25.11@4465.96,2895.17 4465.96,2914.4 4482.83,2931.27 4608.45,2931.27 v1@4622.64,2945.46 ; v1(4622.83,2945.27) 4624.25,2945.27 4666.38,2987.4 4670.32,2987.4 4679.63,2996.71 R107.1@4679.63,3000.65
  Signal Layer 3 w5: v1(3643,2847) 3643,2849.3 3668.48,2874.78 3839.69,2874.78 3856.91,2892 4506.37,2892 4559.64,2945.27 v1(4622.83,2945.27)
  Signal Layer 6 w5: v1(3534.83,2451.27) 3519.83,2466.27 3519.83,2568.1 3544.33,2592.6 3544.33,2708.31 3594,2757.98 3594,2848.75 3605.75,2860.5 3629.5,2860.5 v1(3643,2847) ; v1(4466.34,2021.19) 4466.34,2025.79 4477.83,2037.28 4477.83,2661.02 4500,2683.19 4500,2866.44 4578.83,2945.27 v1(4622.83,2945.27)
  Bottom w5: v1(3534.83,2451.27) 3563.33,2422.77 3563.33,2373.46 3599.81,2336.98 3599.81,2267.27 v2(3584.31,2251.77)
MCU_GPIO154: R59.1 R64.1 U1.C11 | length 1778.9
  Top Layer w5: U1.C11@3568.56,2267.52 v2(3584.31,2283.26) ; v1(3572,2559) 3585.31,2572.31 3792.56,2572.31 3891.1,2473.77 4600.33,2473.77 v1(4682.83,2391.27)
  Signal Layer 6 w5: v1(3572,2559) 3551.69,2559 3537.83,2545.14 3537.83,2488 3567.83,2458 3567.83,2393.77 3584.31,2377.29 v2(3584.31,2283.26)
  Bottom w5: R59.1@4609.44,2428.17 4609.44,2440.63 4628.08,2459.27 4703.34,2459.27 R64.1@4732.39,2430.22 ; v1(4682.83,2391.27) 4686.08,2394.52 4696.69,2394.52 4723.63,2421.46 4723.63,2428.53 4725.32,2430.22 R64.1@4732.39,2430.22 ; R64.1@4734.44,2428.17 R64.1@4732.39,2430.22 ; R64.1@4734.44,2445.72 4732.39,2443.67 R64.1@4732.39,2430.22
MCU_GPIO155: R32.1 R141.1 U1.B11 U25.32 U26.32 | length 2539.4
  Top Layer w5: U1.B11@3568.56,2299.01 3583.93,2314.39 3583.93,2342.83 3612.05,2370.94 3612.05,2401.55 3641.33,2430.84 3641.33,2486.52 3629.33,2498.52 v1(3613.58,2498.52) ; U26.32@4505.33,1860.2 v1(4535.92,1860.2) 4586.44,1809.69 R141.1@4608.81,1809.69 ; U25.32@4505.33,2706.2 4543.9,2706.2 4590.33,2659.77 4604.73,2659.77 R32.1@4608.81,2655.69
  Signal Layer 3 w5: v1(3682.58,2747.34) 3817.89,2747.34 3839.46,2725.77 4524.33,2725.77 v1(4559.83,2690.27)
  Signal Layer 6 w5: v1(3613.58,2498.52) 3613.58,2519.7 3682.58,2588.7 v1(3682.58,2747.34) ; v1(4535.92,1860.2) 4535.92,2077.92 4586.33,2128.33 4586.33,2663.77 v1(4559.83,2690.27)
MCU_GPIO156: R58.2 U1.A11 | length 827.6
  Top Layer w5: U1.A11@3568.56,2330.51 3568.56,2356.1 3593.83,2381.37 v1(3593.83,2427.27) ; v1(4145,2675) 4164.49,2694.49 4181.29,2694.49 R58.2@4184.81,2698.02
  Bottom w5: v1(3593.83,2427.27) 3609.52,2427.27 3667.75,2485.5 3668.31,2485.5 3694.58,2511.77 3709.08,2511.77 3729.85,2491 3865.27,2491 4049.27,2675 v1(4145,2675)
MCU_GPIO157: R112.2 R120.1 U1.E10 | length 1493.4
  Top Layer w5: U1.E10@3537.06,2204.52 v2(3552.81,2220.27) ; v1@4147.83,2761.27 4163.75,2745.35 4184.81,2745.35 R120.1@4182.15,2742.69
  Signal Layer 3 w5: v1(3472.7,2739.43) 3512.55,2779.27 3667.27,2779.27 3688.77,2800.77 4109.23,2800.77 v1(4147,2763)
  Signal Layer 6 w5: v1@3476.07,2736.07 3392.33,2652.33 3392.33,2488.68 3400.24,2480.77 3444.23,2480.77 3463.83,2461.17 3463.83,2371.81 3536.78,2298.86 3536.78,2289.71 3536.81,2245.35 ; 3536.78,2245.31 3536.78,2236.3 v2(3552.81,2220.27)
  Bottom w5: R112.2@4112.21,2804.9 4112.21,2781.79 4131,2763 v1(4147,2763)
MCU_GPIO158: R87.2 U1.D10 | length 1001.5
  Top Layer w5: U1.D10@3537.06,2236.02 v2(3552.81,2251.77) ; v1(4122,2619) 4153.13,2619 R87.2@4184.81,2650.69
  Signal Layer 3 w5: v1(3534.83,2423.27) 3537.22,2425.66 3548.6,2425.66 3573.88,2450.94 3573.88,2500.3 3709.35,2635.77 4105.23,2635.77 v1(4122,2619)
  Bottom w5: v1(3534.83,2423.27) 3549.21,2408.89 3549.21,2408.64 3554.33,2403.52 3554.33,2369.73 3568.81,2355.26 3568.81,2267.76 v2(3552.81,2251.77)
MCU_GPIO159: R86.2 U1.C10 | length 1136.1
  Top Layer w5: U1.C10@3537.06,2267.52 v2(3552.81,2283.26) ; v1(4285.44,2529.69) R86.2@4285.44,2568.06
  Top Layer w6.25: R86.2@4284.44,2569.06 R86.2@4285.44,2568.06
  Signal Layer 3 w5: v1(3533.33,2395.18) 3588.82,2395.18 3637.83,2444.19 3637.83,2538.79 3716.81,2617.77 3785.28,2617.77 3850.29,2552.77 4110.77,2552.77 4132.35,2574.35 4240.77,2574.35 4270.12,2545 v1(4285.44,2529.69)
  Signal Layer 6 w5: v1(3533.33,2395.18) 3552.81,2375.69 v2(3552.81,2283.26)
MCU_GPIO160: R84.2 U1.B10 | length 1119.9
  Top Layer w5: U1.B10@3537.06,2299.01 3552.98,2314.93 3552.98,2359.29 3574.33,2380.64 3574.33,2439.5 3590.04,2455.2 v1(3591.38,2455.2) ; v1(4333.44,2529.69) R84.2@4333.44,2567.74
  Top Layer w6.25: R84.2@4332.12,2569.06 R84.2@4333.44,2567.74
  Signal Layer 3 w5: v1(3591.38,2455.2) 3591.38,2505.07 3713.08,2626.77 3789.01,2626.77 3854.01,2561.77 4107.04,2561.77 4128.75,2583.48 4279.64,2583.48 v1(4333.44,2529.69)
MCU_GPIO161: R83.2 U1.E9 | length 1511.2
  Top Layer w5: U1.E9@3505.57,2204.52 v2(3521.31,2220.27) ; v1(4378,2534) R83.2@4378,2567.27
  Top Layer w6.25: R83.2@4378,2567.27 R83.2@4379.8,2569.06
  Signal Layer 3 w5: v1(3425.58,2460.32) 3427.82,2458.08 3439.5,2458.08 3454.83,2442.75 3454.83,2383.79 3479.17,2359.45 3578.55,2359.45 3656.33,2437.24 3656.33,2492.52 3684.58,2520.77 3739.77,2520.77 3761.22,2542.22 3835.37,2542.22 3842.83,2534.77 3991.86,2534.77 4022.86,2503.77 4347.77,2503.77 v1(4378,2534)
  Signal Layer 6 w5: v1(3425.58,2460.32) 3439.41,2460.32 3454.83,2444.9 3454.83,2368.08 3496.81,2326.1 3496.81,2244.77 v2(3521.31,2220.27)
MCU_GPIO162: R115.1 R127.2 U1.A8 | length 1408.9
  Top Layer w5: U1.A8@3474.07,2330.51 3472.65,2331.93 3472.65,2390.34 v1(3489.83,2407.52) ; v1(4154,2553) 4208.81,2607.81 4208.81,2910.69 R115.1@4184.81,2934.69
  Signal Layer 3 w5: v1@3496.28,2405.02 3532.84,2368.45 3574.82,2368.45 3646.83,2440.46 3646.83,2535.06 3720.54,2608.77 3781.56,2608.77 3846.56,2543.77 4114.49,2543.77 4132.23,2561.5 4143.13,2561.5 4151.63,2553 v1(4154,2553)
  Bottom w5: v1(4154,2553) 4194,2553 R127.2@4197,2556
MCU_GPIO163: R114.1 U1.B8 | length 1284.8
  Top Layer w5: U1.B8@3474.07,2299.01 3458.7,2314.39 3458.7,2359.49 3463.65,2364.44 3463.65,2435.34 v1(3494.14,2465.83) ; v1(4141,2943) 4141,2916 4165.06,2891.94 4184.38,2891.94 R114.1@4185.38,2890.95
  Signal Layer 3 w5: v1(3574,2837) 3604,2867 3629.78,2892.78 3832.24,2892.78 3876.96,2937.5 4130.9,2937.5 4136.4,2943 v1(4141,2943)
  Signal Layer 6 w5: v1(3494.14,2465.83) 3494.14,2466.14 3505,2477 3505,2768 v1(3574,2837)
MCU_GPIO164: R88.1 R119.1 U1.C8 | length 1220.4
  Top Layer w5: v2(3458.32,2283.26) U1.C8@3474.07,2267.52 ; v1(4127,2698) 4127,2803.81 4163.21,2840.02 R119.1@4184.81,2840.02
  Signal Layer 3 w5: v1(3485.83,2493.27) 3505.83,2513.27 3505.83,2552.56 3616.04,2662.77 4095.33,2662.77 4127,2694.44 v1(4127,2698)
  Bottom w5: v2(3458.32,2283.26) 3458.32,2284.68 3466.33,2292.69 3466.33,2473.77 v1(3485.83,2493.27) ; R88.1@4107.62,2737 4108.23,2736.39 4108.23,2716.77 v1(4127,2698)
MCU_GPIO165: R126.1 R128.2 U1.F6 | length 2494.3
  Top Layer w5: v2(3395.33,2188.77) U1.F6@3411.08,2173.03 ; v1(4485.83,3085.27) 4485.83,3051.22 R126.1@4496.74,3040.31
  Signal Layer 3 w5: v1(3498.57,3046) 3620,3046 3657.77,3083.77 3977.64,3083.77 3990.14,3071.27 4424.27,3071.27 4444,3091 4475.5,3091 4481.23,3085.27 v1(4485.83,3085.27)
  Signal Layer 6 w5: v2(3395.33,2188.77) 3411.33,2204.77 3411.33,2292.16 3366.4,2337.09 3366.4,2444.06 3307.22,2503.23 3307.22,2702.22 3357,2752 3357,3016.55 3396.45,3056 3488.57,3056 v1(3498.57,3046)
  Bottom w5: v1(4485.83,3085.27) 4525.1,3046 4758.73,3046 4772.32,3059.59 R128.2@4807.68,3059.59
MCU_GPIO166: R113.2 R116.1 U1.B5 | length 2274.2
  Top Layer w5: U1.B5@3379.58,2299.01 3363.83,2314.76 3363.83,2343.33 3350.83,2356.33 3350.83,2438.27 v1(3413.83,2501.27) ; v1(4528.83,3082.27) 4528.83,3081.14 4538.83,3071.14 R116.1@4538.83,3037.25
  Signal Layer 3 w5: v1(3581,3065) 3608.77,3092.77 3967.33,3092.77 3982.99,3108.43 4010.57,3108.43 4038.73,3080.27 4420.54,3080.27 4444.04,3103.77 4507.33,3103.77 v1(4528.83,3082.27)
  Signal Layer 6 w5: v1(3413.83,2501.27) 3492.83,2580.27 3492.83,2788.42 3555.09,2850.68 3555.09,2904.09 3631.53,2980.53 3631.53,3017.29 3583.82,3065 v1(3581,3065)
  Bottom w5: v1(4528.83,3082.27) 4556.1,3055 4755,3055 R113.2@4807.81,3107.81
MCU_GPIO167: R111.1 R117.1 U1.E5 | length 2476.1
  Top Layer w5: v2(3363.83,2220.27) U1.E5@3379.58,2204.52 ; R111.1@4585.38,3231 4585.38,3101.72 v1(4585.83,3101.27) R117.1@4585.83,3043.36
  Signal Layer 6 w5: v2(3363.83,2220.27) 3348.33,2235.77 3348.33,2294.77 3341.83,2301.27 3341.83,2443.17 3281.33,2503.67 3281.33,2783.6 3339,2841.27 3339,2947.27 3290.83,2995.44 3290.83,3064.1 3332.23,3105.5 3581.5,3105.5 3618,3142 4545.1,3142 v1(4585.83,3101.27)
MCU_GPIO168: R89.1 R118.1 U1.F5 | length 2551.8
  Top Layer w5: v2(3363.83,2188.77) U1.F5@3379.58,2173.03 ; R118.1@4630.62,3047.89 4629.83,3048.68 v1(4629.83,3078.27) 4643.38,3091.82 R89.1@4643.38,3231
  Signal Layer 6 w5: v2(3363.83,2188.77) 3379.33,2204.27 3379.33,2298 3355,2322.33 3355,2442.73 3290.33,2507.4 3290.33,2779.88 3348,2837.54 3348,2951 3299.83,2999.17 3299.83,3060.38 3335.96,3096.5 3790.56,3096.5 3825.83,3131.77 4508.33,3131.77 4561.83,3078.27 v1(4629.83,3078.27)
MCU_GPIO222/TDI: EC1.8 U1.T12 U7.18 | length 4579.1
  Top Layer w5: v1(3584.91,1582.57) 3600.06,1597.72 U1.T12@3600.06,1858.07
  Signal Layer 3 w5: v1(3161.63,2563) 2954,2355.37 2954,2317.37 2678.9,2042.27 1939.27,2042.27 1840,1943 1840,1645 2024,1461 2024,1335 2107.42,1251.58 2139.58,1251.58 v1(2141,1253) 2144,1250 2460.18,1250 2788.68,1578.5 3012.29,1578.5 3048.52,1542.27 3296.31,1542.27 3318.93,1519.64 3506.1,1519.64 3562.2,1575.74 3575.95,1575.74 v1@3577.15,1576.95
  Bottom w5: EC1.8@2140.04,1135.27 2140.04,1252.04 v1(2141,1253) ; v1(3161.63,2563) 3218.1,2563 3230.08,2551.02 U7.18@3277.24,2551.02
MCU_GPIO223/TDO: EC1.6 U1.R12 U7.8 | length 4838.1
  Top Layer w5: v1(3520.87,1591.69) 3522.22,1590.33 3544.74,1590.33 3571.08,1564 3596,1564 3615.43,1583.43 3615.43,1874.19 U1.R12@3600.06,1889.56
  Signal Layer 3 w5: v1(3109.78,2660.48) 3134.82,2685.52 3196,2685.52 3236,2645.52 3236,2585.76 2981,2330.76 2981,2306.19 2690.08,2015.27 1954.45,2015.27 1867,1927.82 1867,1656.18 2052,1471.18 2052,1399.6 2083.6,1368 v1(2085,1368) 2102,1351 2523,1351 2777.73,1605.73 3024.51,1605.73 3060.98,1569.27 3307.49,1569.27 3330.11,1546.64 3475.83,1546.64 v1(3520.87,1591.69)
  Bottom w5: v1(2085,1368) 2086.5,1366.5 2086.5,1244.5 2109.61,1221.39 EC1.6@2109.61,1138.69 ; U7.8@3056.76,2678.98 3091.28,2678.98 v1(3109.78,2660.48)
MCU_TCK: EC1.5 U1.R13 U7.14 | length 4697.1
  Top Layer w5: EC1.5@2108.54,1135.27 2108.54,1311.94 2114,1317.4 v1(2114,1322) ; U1.R13@3631.55,1889.56 3646.93,1874.19 3646.93,1750.38 3661.15,1736.15 3661.15,1721.26 3638.97,1699.08 v1@3638.81,1699.08
  Signal Layer 3 w5: v1(3181.52,2599) 3182.12,2598.39 3182.12,2557.34 2963,2338.22 2963,2313.64 2682.63,2033.27 1947,2033.27 1849,1935.27 1849,1648.73 2034,1463.73 2034,1343 2055,1322 v1(2114,1322) 2519.46,1322 2784.96,1587.5 2797.5,1587.5 2797.73,1587.73 3015.79,1587.73 3052.25,1551.27 3300.04,1551.27 3322.66,1528.64 3502.37,1528.64 3578.48,1604.75 3608.77,1604.75 3624,1619.98 3624,1689.87 v1@3636.27,1702.14
  Bottom w5: v1(3181.52,2599) 3181.52,2603.6 3186.65,2608.73 3186.65,2610.03 3230,2653.39 U7.14@3277.24,2653.39
  other v1: 3635.36,1698.48
MCU_TMS: EC1.3 R202.1 U1.T13 U7.16 | length 4697.4
  Top Layer w5: v1(2069,1340) 2069,1336.62 2077.05,1328.57 EC1.3@2077.05,1135.27 ; v1@3631.55,1739.4 U1.T13@3631.55,1858.07
  Signal Layer 3 w5: v1(2069,1340) 2524.73,1340 2781.46,1596.73 3020.79,1596.73 3057.25,1560.27 3303.76,1560.27 3326.39,1537.64 3498.64,1537.64 3574.75,1613.75 3602.12,1613.75 3610.32,1621.96 3610.32,1704.76 v1(3634.64,1729.08) ; v1@2069.5,1339.5 2043,1366 2043,1467.46 1858,1652.46 1858,1931.54 1950.72,2024.27 2686.35,2024.27 2972,2309.91 2972,2334.49 3210.34,2572.83 v1@3210.34,2603.87
  Bottom w5: v1@3210.34,2603.87 3275.57,2603.87 U7.16@3277.24,2602.2 ; v1(3634.64,1729.08) 3678.09,1729.08 3703.86,1703.3 3725.9,1703.3 3747.31,1724.69 R202.1@3750.87,1724.69
  other v1: 3213.06,2604.08
MCU_XRSn: C38.1 EC1.120 R42.1 R44.1 R49.1 R55.1 R82.2 S4.4 TP10.1 U1.G14 | length 3341.2
  Top Layer w5: U1.G14@3663.05,2141.53 v2(3678.79,2157.28) ; S4.4@3880.32,3217.44 3894.37,3203.39 3902.61,3203.39 3923,3183 4215.1,3183 4232.33,3165.77 4232.33,3150.27 4261.83,3120.76 4261.83,3043.27 4243.34,3024.77 4231.13,3024.77 4231.13,3024.97 4200.83,3055.27 4145.83,3055.27 4143.25,3052.69 4143.19,3052.69 4138.8,3048.3 4138.8,3048.24 4122,3031.44 4122,2854.72 4104.28,2837 4034.7,2837 4016,2818.3 R44.1@4016,2805.5 4016,2775.98 4055,2736.98 v1(4055,2694) ; TP10.1@3925.83,2239.27 3965.1,2200 R82.2@3999.21,2200
  Signal Layer 6 w5: v1(4055,2694) 4067,2682 4067,2314.44 4017.33,2264.77 3951.33,2264.77 TP10.1@3925.83,2239.27 3990.26,2174.84 3990.26,2003.52 4033.01,1960.77 4069.23,1960.77 4099,1931 4099,1882.05 4099.33,1881.72 4099.33,1764.6 4099,1764.27 4099,1710.1 4128.5,1680.6 4128.5,1545.5 v1(4102,1519)
  Bottom w5: v2(3678.79,2157.28) 3681.28,2154.79 3687.7,2154.79 3688.22,2154.27 3855.27,2154.27 3915.07,2214.07 3915.07,2216.33 3917.22,2218.48 3917.22,2230.66 TP10.1@3925.83,2239.27 ; EC1.120@4029.8,1135.27 4029.8,1379.18 C38.1@4049,1398.38 ; C38.1@4058.31,1389.07 C38.1@4049,1398.38 ; v1(4102,1519) 4102,1450.62 R42.1@4098,1446.62 4097.24,1446.62 C38.1@4049,1398.38
MID_RXD: U6.13 U7.11 | length 428.7
  Top Layer w5: U6.13@2949.09,2572.56 3036.85,2572.56 3049,2584.71 3049,2628 3100,2679 3152,2679 v1(3164,2667)
  Bottom w5: v1(3164,2667) 3191.52,2694.52 3227.16,2730.16 U7.11@3277.24,2730.16
MID_TCK_SWDCLK: U6.12 U7.6 | length 178.2
  Top Layer w5: U6.12@2949.09,2547.56 2988.96,2547.56 2995.4,2554 v1(3000,2554)
  Bottom w5: v1(3000,2554) 3000,2557.92 2992.49,2565.43 2992.49,2599.49 3020.7,2627.7 3056.67,2627.7 U7.6@3056.76,2627.8
MID_TDI: U6.15 U7.2 | length 250.8
  Top Layer w5: U6.15@2949.09,2622.56 2952.49,2625.95 v1(2994.1,2625.95)
  Signal Layer 3 w5: v1(2994.1,2625.95) 2995.15,2627 3022.56,2627 3104.44,2545.12 v1(3104.44,2538.54)
  Bottom w5: U7.2@3056.76,2525.43 3058.34,2527.01 3092.91,2527.01 v1(3104.44,2538.54)
MID_TDO_SWO: U6.10 U7.12 | length 475.5
  Top Layer w5: U6.10@2949.09,2497.56 2992.84,2497.56 3002.4,2488 v1(3007,2488)
  Bottom w5: v1(3007,2488) 3008.56,2486.44 3097.8,2486.44 3132,2520.64 3132,2610 3226.57,2704.57 U7.12@3277.24,2704.57
MID_TMS_JTAG: U6.14 U7.4 | length 116.4
  Top Layer w5: U6.14@2949.09,2597.56 3004.1,2597.56 v1(3009.99,2591.67)
  Bottom w5: v1(3009.99,2591.67) 3025.04,2576.61 U7.4@3056.76,2576.61
MID_TXD: U6.11 U7.7 | length 261.9
  Top Layer w5: U6.11@2949.09,2522.56 2949.53,2523 v1(2995,2523)
  Bottom w5: v1(2995,2523) 2969,2549 2969,2631 2981.45,2643.45 3004.45,2643.45 3014.39,2653.39 U7.7@3056.76,2653.39
NetB1_2: B1.2 R73.2 R74.1 | length 208.4
  Bottom w5: B1.2@5061.29,2589.89 5096.06,2589.89 5134.44,2628.27 R73.2@5134.44,2698.79 5182.41,2698.79 R74.1@5183,2699.38
NetB1_3: B1.3 R65.1 | length 113.6
  Bottom w5: B1.3@5061.29,2615.48 5082.81,2615.48 5101,2633.68 5101,2673.55 5084.44,2690.12 R65.1@5084.44,2693.16
NetB1_5: B1.5 R68.1 | length 100
  Bottom w5: R68.1@5232.44,2693.16 5232.44,2663.69 5255.05,2641.07 B1.5@5293.58,2641.07
NetB1_8: B1.8 R67.1 | length 83.9
  Bottom w5: B1.8@5298.28,2569 B1.8@5293.58,2564.3 5345.51,2564.3 R67.1@5363.44,2546.37
NetC1_1: C1.1 R7.2 U2.96 | length 222.7
  Top Layer w5: v1(2243.87,2800.69) 2273.87,2800.69 2316.25,2800.69 R7.2@2317.87,2802.31
  Bottom w6.25: U2.96@2107.7,2829.35 2215.21,2829.35 v1(2243.87,2800.69)
NetC10_1: C10.1 C11.1 C12.1 U2.87 U2.115 | length 654.3
  Bottom w6.25: U2.87@2107.7,2687.62 2332.62,2687.62 2450.22,2805.22 U2.115@2450.22,2888.41 2450.22,2946.57 2459.65,2956 2468.09,2964.44 2469.09,2965.44 2516.09,2965.44 C10.1@2564.09,2965.44
NetC13_1: C13.1 U2.89 Y1.3 | length 274.7
  Bottom w5: Y1.3@1919.37,2852.99 1919.37,2832.05 1940.73,2810.69 2013.16,2810.69 2013.22,2810.75 2023,2800.97 C13.1@2023,2787.38 ; C13.1@2022.28,2786.66 2025.64,2783.29 2025.64,2765.92 2072.44,2719.12 U2.89@2107.7,2719.12
NetC14_1: C14.1 U2.88 Y1.1 | length 327.3
  Bottom w5: Y1.1@1843.5,2753.69 1862.98,2773.17 1862.98,2783.98 1874,2795 C14.1@1965.94,2795 ; C14.1@1973.87,2787.06 1973.87,2765.13 2035.31,2703.69 U2.88@2107.87,2703.69
NetC15_1: C15.1 R13.1 U2.68 | length 217.1
  Bottom w5: C15.1@1988.87,2454.31 2013.57,2429.61 2053.95,2429.61 2064.87,2418.69 2064.87,2392.07 2068.53,2388.41 U2.68@2107.7,2388.41 ; C15.1@1988.87,2454.69 R13.1@1988.87,2510.06
NetC19_1: C19.1 U8.4 | length 153.7
  Top Layer w5: U8.4@2028.05,2483.28 2097.72,2483.28 2118,2463 C19.1@2118,2407.62
NetC39_1: C39.1 U11.3 | length 69.2
  Top Layer w6.25: C39.1@3759.11,2986 C39.1@3767.62,2986 3780.04,2973.58 U11.3@3823.17,2973.58
NetC41_2: C41.2 R51.1 U12.2 | length 688.1
  Top Layer w5: v1@3893.6,3066 3901.97,3074.37 3935.97,3074.37 U12.2@3936.81,3073.53 ; R51.1@3983.87,2651.06 4009.94,2651.06 4029.7,2631.3 v1(4029.7,2608.75) 4045.83,2592.62 C41.2@4068,2592.62
  Signal Layer 6 w5: v1(3887.04,3062.19) 3888.65,3062.19 3973,2977.85 3973,2665.45 v1(4029.7,2608.75) ; v1@4029.7,2606.25 v1@4035.75,2606.25
NetC42_2: C42.2 R54.1 U12.4 | length 664.4
  Top Layer w5: v1(3902.83,3023.27) 3914.56,3035 U12.4@3937.32,3035 ; R54.1@3936.87,2651.06 3936.87,2613.13 3958,2592 3981.38,2592 C42.2@3983,2593.62 3993.62,2583 v1(4021,2583)
  Signal Layer 6 w5: v1(3902.83,3023.27) 3964,2962.1 3964,2640 v1(4021,2583)
NetC48_1: C48.1 R30.1 R95.2 R97.2 | length 401.7
  Bottom w5: C48.1@5507,1662.53 5507,1686 5543.4,1722.4 5610.23,1722.4 5617.65,1714.97 5617.65,1699.38 5618.44,1698.59 R95.2@5618.44,1657.83 ; R97.2@5618.44,1798.69 5653.44,1798.69 5686.44,1765.69 5686.44,1740.69 5644.34,1698.59 R30.1@5618.63,1698.59
NetC48_2: C48.2 C49.1 L1.2 R2.1 R30.2 R94.2
NetC50_1: C50.1 R102.1 R206.2 U15.1 | length 309.2
  Top Layer w5: v1(5476,1893) 5544.75,1961.75 5554.75,1961.75 v1(5558,1965)
  Bottom w5: U15.1@5445.28,1870.37 5452.66,1870.37 5475.29,1893 v1(5476,1893) ; C50.1@5502.44,2004.16 5508.19,1998.4 R206.2@5571.19,1998.4 ; v1(5558,1965) 5571.19,1978.19 R206.2@5571.19,1998.4 ; R102.1@5571.19,2045.69 R206.2@5571.19,1998.4
NetC50_2: C50.2 C125.1 L2.2 R101.1 R102.2
NetC52_2: C52.2 R99.1 U15.8 | length 163.7
  Bottom w5: C52.2@5248,1876.68 5248,1829.26 5249.64,1830.9 5264.4,1830.9 5264.5,1831 U15.8@5363.59,1831
NetC63_2: C63.2 R199.1 | length 65.1
  Top Layer w5: C63.2@2992.5,1971.86 3000.38,1963.98 R199.1@3000.38,1910
NetC87_2: C87.2 C88.2 J5.5 | length 321
  Top Layer w6.25: v1(4788,2803) 4791.01,2806.01 4804.85,2806.01 4817.8,2818.96 4896.34,2818.96 J5.5@4903.31,2825.92
  Bottom w5: v1(4788,2803) 4819.35,2834.35 4894.89,2834.35 C88.2@4912.38,2851.84 4911.38,2852.84 C87.2@4911.38,2903
NetC89_1: C89.1 C90.1 U25.2 | length 168.8
  Top Layer w5: U25.2@4530.92,2751.47 4601.11,2751.47 C90.1@4608.21,2744.37 ; C90.1@4608.21,2745.27 C90.1@4608.21,2744.37 ; C89.1@4608.81,2697.86 4608.21,2698.47 C90.1@4608.21,2744.37 ; C89.1@4608.81,2703.69 4608.81,2743.77 C90.1@4608.21,2744.37
NetC95_2: C95.2 C96.2 J5.6 | length 224.5
  Top Layer w6.25: v1@4798,2777 4798.9,2777.9 4895.44,2777.9 J5.6@4903.31,2785.76
  Bottom w5: v1(4799.39,2775.55) 4825.84,2802 C96.2@4852.38,2802 ; C95.2@4856.32,2752 C96.2@4856.32,2798.06
  Bottom w6.25: C96.2@4852.38,2802 C96.2@4856.32,2798.06
NetC97_1: C97.1 C98.1 R131.2 U25.3 | length 235.7
  Top Layer w12: U25.3@4530.92,2771.16 4531.45,2771.69 v1@4567.44,2771.69
  Bottom w12: v1(4567,2771) 4595.08,2742.92 C97.1@4595.08,2672.42 ; C97.1@4608.66,2683.2 4609.66,2682.2 C98.1@4655.66,2682.2 4689.58,2682.2 R131.2@4694.83,2676.95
